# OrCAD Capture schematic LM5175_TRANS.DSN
size E; title: LM5175 42-V Wide VIN Synchronous 4-Switch Buck-Boost; rev: 1.0; note: Datasheet: SNVSA37A  EVM: SNVU440A; note: Synchronous Step Down Converter
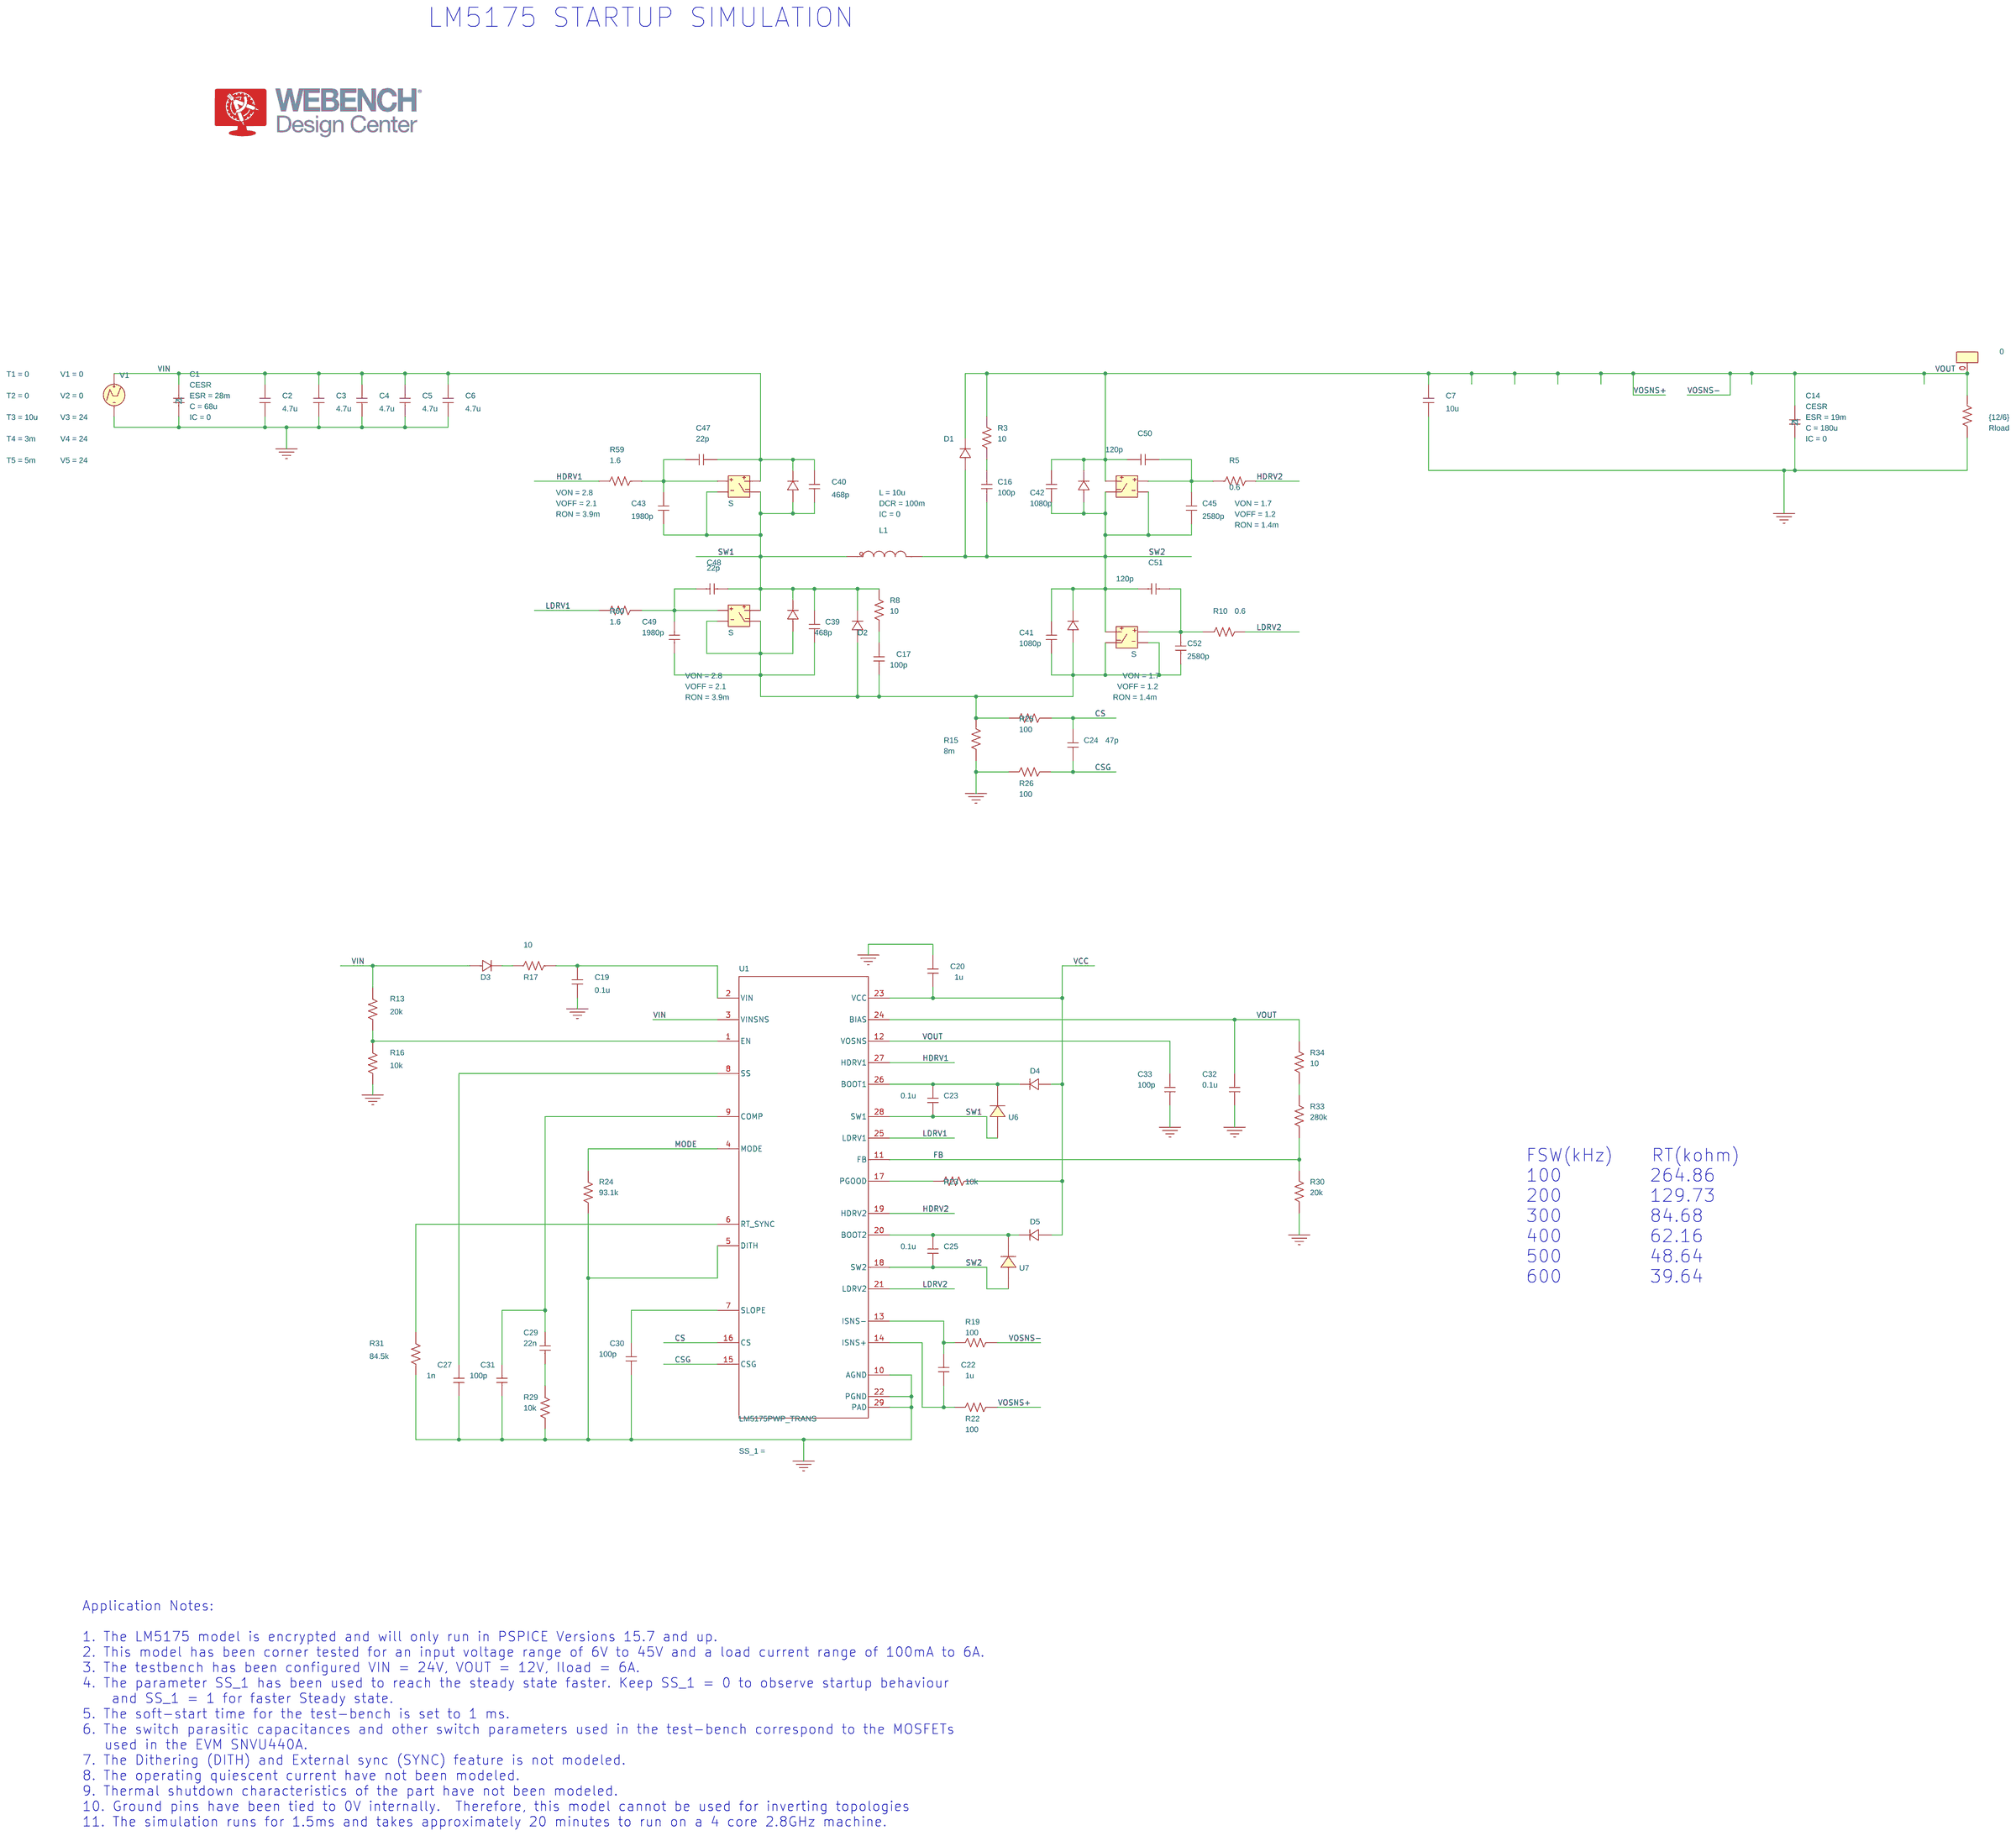
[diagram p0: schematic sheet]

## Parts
C1  CESR
C2  4.7u  [RAD/CK05]
C3  4.7u  [RAD/CK05]
C4  4.7u  [RAD/CK05]
C5  4.7u  [RAD/CK05]
C6  4.7u  [RAD/CK05]
C7  10u  [RAD/CK05]
C14  CESR
C16  100p  [RAD/CK05]
C17  100p  [RAD/CK05]
C19  0.1u  [RAD/CK05]
C20  1u  [RAD/CK05]
C22  1u  [RAD/CK05]
C23  0.1u  [RAD/CK05]
C24  47p  [RAD/CK05]
C25  0.1u  [RAD/CK05]
C27  1n  [RAD/CK05]
C29  22n  [RAD/CK05]
C30  100p  [RAD/CK05]
C31  100p  [RAD/CK05]
C32  0.1u  [RAD/CK05]
C33  100p  [RAD/CK05]
C39  468p  [RAD/CK05]
C40  468p  [RAD/CK05]
C41  1080p  [RAD/CK05]
C42  1080p  [RAD/CK05]
C43  1980p  [RAD/CK05]
C45  2580p  [RAD/CK05]
C47  22p  [RAD/CK05]
C48  22p  [RAD/CK05]
C49  1980p  [RAD/CK05]
C50  120p  [RAD/CK05]
C51  120p  [RAD/CK05]
C52  2580p  [RAD/CK05]
D1  Dbreak
D2  Dbreak
D3  Dbreak
D4  Dbreak
D5  Dbreak
D_Body1  Dbreak
D_Body3  Dbreak
D_Body4  Dbreak
D_Body5  Dbreak
IC1  0
L1  LDCR
R3  10  [AX/RC05]
R5  0.6  [AX/RC05]
R8  10  [AX/RC05]
R10  0.6  [AX/RC05]
R13  20k  [AX/RC05]
R15  8m  [AX/RC05]
R16  10k  [AX/RC05]
R17  10  [AX/RC05]
R19  100  [AX/RC05]
R22  100  [AX/RC05]
R23  10k  [AX/RC05]
R24  93.1k  [AX/RC05]
R25  100  [AX/RC05]
R26  100  [AX/RC05]
R29  10k  [AX/RC05]
R30  20k  [AX/RC05]
R31  84.5k  [AX/RC05]
R33  280k  [AX/RC05]
R34  10  [AX/RC05]
R59  1.6  [AX/RC05]
R60  1.6  [AX/RC05]
Rload  {12/6}  [AX/RC05]
S1  S
S2  S
S3  S
S6  S
U1  LM5175PWP_TRANS  [PWP0028F_N]
U6  D_D
U7  D_D
V1  VPWL

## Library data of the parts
C1 = CESR_1: C: 68u; ESL: 0; ESR: 28m; IC: 0; PSpiceTemplate: X^@REFDES %1 %2 @MODEL PARAMS: ?C|C=@C||C=10U| ?ESR|ESR=@ESR||ESR=2M| ?IC|IC=@IC||IC=1N| ?X|X=@X||X=1|; X: 1
C2-C7 C16 C17 C19 C20 C22-C25 C27 C29-C33 C39-C43 C45 C47-C52 = C: IC: 0
C14 = CESR: C: 180u; ESL: 0; ESR: 19m; IC: 0; PSpiceTemplate: X^@REFDES %1 %2 @MODEL PARAMS: ?C|C=@C||C=10U| ?ESR|ESR=@ESR||ESR=2M| ?IC|IC=@IC||IC=1N| ?X|X=@X||X=1|; X: 1
D1-D5 D_Body1 D_Body3-D_Body5 = Dbreak
IC1 = IC1
L1 = LDCR_0: DCR: 100m; IC: 0; L: 10u; PSpiceTemplate: X^@REFDES %IN %OUT @MODEL PARAMS:  ?L|L=@L||L=1u|  ?DCR|DCR=@DCR||DCR=0.01| ?IC|IC=@IC||IC=0|
R3 R5 R8 R10 R13 R15-R17 R19 R22-R26 R29-R31 R33 R34 R59 R60 Rload = R
S1 S2 = S: ROFF: 10e10; RON: 1.4m; VOFF: 1.2; VON: 1.7
S3 S6 = S: ROFF: 10e10; RON: 3.9m; VOFF: 2.1; VON: 2.8
U1 = LM5175PWP_TRANS
U6 = D_D
U7 = D_D_1
V1 = VPWL: PSpiceTemplate: V^@REFDES %+ %- ?DC|DC @DC| ?AC|AC @AC|\n+PWL @T1 @V1 @T2 @V2 #T3/@T3 @V3/ #T4/@T4 @V4/ #T5/@T5 @V5/ #T6/@T6 @V6/ #T7/@T7 @V7/ #T8/@T8 @V8/ #T9/@T9 @V9/ #T10/@T10 @V10/; T1: 0; T2: 0; T3: 10u; T4: 3m; T5: 5m; V1: 0; V2: 0; V3: 24; V4: 24; V5: 24

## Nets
VCC: C20.2 D4.0(1) D5.0(1) R23.1 U1.23(VCC)
VIN: C1.1 C2.1 C3.1 C4.1 C5.1 C6.1 C40.1 C47.2 D3.0(1) D_Body1.1(2) R13.1 S3.2(3) U1.3(VINSNS) V1.1(+)
0: C1.2 C2.2 C3.2 C4.2 C5.2 C6.2 C7.2 C14.2 C19.2 C20.1 C27.2 C30.2 C31.2 C32.2 C33.2 R15.1 R16.2 R24.2 R26.2 R29.2 R30.1 R31.2 Rload.1 U1.5(DITH) U1.10(AGND) U1.22(PGND) U1.29(PAD) V1.2(-)
CS: C24.1 R25.1 U1.16(CS)
CSG: C24.2 R26.1 U1.15(CSG)
FB: R30.2 R33.1 U1.11(FB)
HDRV1: R59.2 U1.27(HDRV1)
HDRV2: R5.2 U1.19(HDRV2)
LDRV1: R60.2 U1.25(LDRV1)
LDRV2: R10.2 U1.21(LDRV2)
MODE: R24.1 U1.4(MODE)
SW1: C23.2 C39.1 C40.2 C43.2 C48.2 D2.1(2) D_Body1.0(1) D_Body3.1(2) L1.1(IN) R8.2 S3.1(2) S3.3(4) S6.2(3) U1.28(SW1) U6.1
SW2: C16.2 C25.2 C41.1 C42.2 C45.2 C51.1 D1.0(1) D_Body4.0(1) D_Body5.1(2) L1.3(OUT) S1.2(3) S2.1(2) S2.3(4) U1.18(SW2) U7.1
VOSNS+: C7.1 C14.1 C32.1 C33.1 C42.1 C50.1 D1.1(2) D_Body4.1(2) IC1.0(+) R3.2 R19.1 R22.1 R34.2 Rload.2 S2.2(3) U1.12(VOSNS) U1.24(BIAS)
N17042744: C51.2 C52.1 R10.1 S1.0(1)
N17042777: C17.2 C39.2 C41.2 C49.2 C52.2 D2.0(1) D_Body3.0(1) D_Body5.0(1) R15.2 R25.2 S1.1(2) S1.3(4) S6.1(2) S6.3(4)
N17042896: C48.1 C49.1 R60.1 S6.0(1)
N17042900: C43.1 C47.1 R59.1 S3.0(1)
N17042980: C17.1 R8.1
N17043335: C45.1 C50.2 R5.1 S2.0(1)
N17044182: C16.1 R3.1
N17047006: C19.1 R17.1 U1.2(VIN)
N17047008: C22.1 R19.2 U1.13(ISNS-)
N17047033: D3.1(2) R17.2
N17047060: R13.2 R16.1 U1.1(EN)
N17047115: C29.1 C31.1 U1.9(COMP)
N17047124: C27.1 U1.8(SS)
N17047136: C29.2 R29.1
N17047190: R31.1 U1.6(RT_SYNC)
N17047321: C30.1 U1.7(SLOPE)
N17047339: C25.1 D5.1(2) U1.20(BOOT2) U7.2
N17047361: C23.1 D4.1(2) U1.26(BOOT1) U6.2
N17047421: R23.2 U1.17(PGOOD)
N17047490: C22.2 R22.2 U1.14(ISNS+)
N17047624: R33.2 R34.1

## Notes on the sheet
- LM5175 STARTUP SIMULATION
- FSW(kHz)    RT(kohm)
  100	        264.86
  200	        129.73
  300	        84.68
  400	        62.16
  500	        48.64
  600	        39.64
- Application Notes:
  1. The LM5175 model is encrypted and will only run in PSPICE Versions 15.7 and up.
  2. This model has been corner tested for an input voltage range of 6V to 45V and a load current range of 100mA to 6A.
  3. The testbench has been configured VIN = 24V, VOUT = 12V, Iload = 6A.
  4. The parameter SS_1 has been used to reach the steady state faster. Keep SS_1 = 0 to observe startup behaviour
      and SS_1 = 1 for faster Steady state.
  5. The soft-start time for the test-bench is set to 1 ms.
  6. The switch parasitic capacitances and other switch parameters used in the test-bench correspond to the MOSFETs
     used in the EVM SNVU440A.
  7. The Dithering (DITH) and External sync (SYNC) feature is not modeled.
  8. The operating quiescent current have not been modeled.
  9. Thermal shutdown characteristics of the part have not been modeled.
  10. Ground pins have been tied to 0V internally.  Therefore, this model cannot be used for inverting topologies
  11. The simulation runs for 1.5ms and takes approximately 20 minutes to run on a 4 core 2.8GHz machine.
